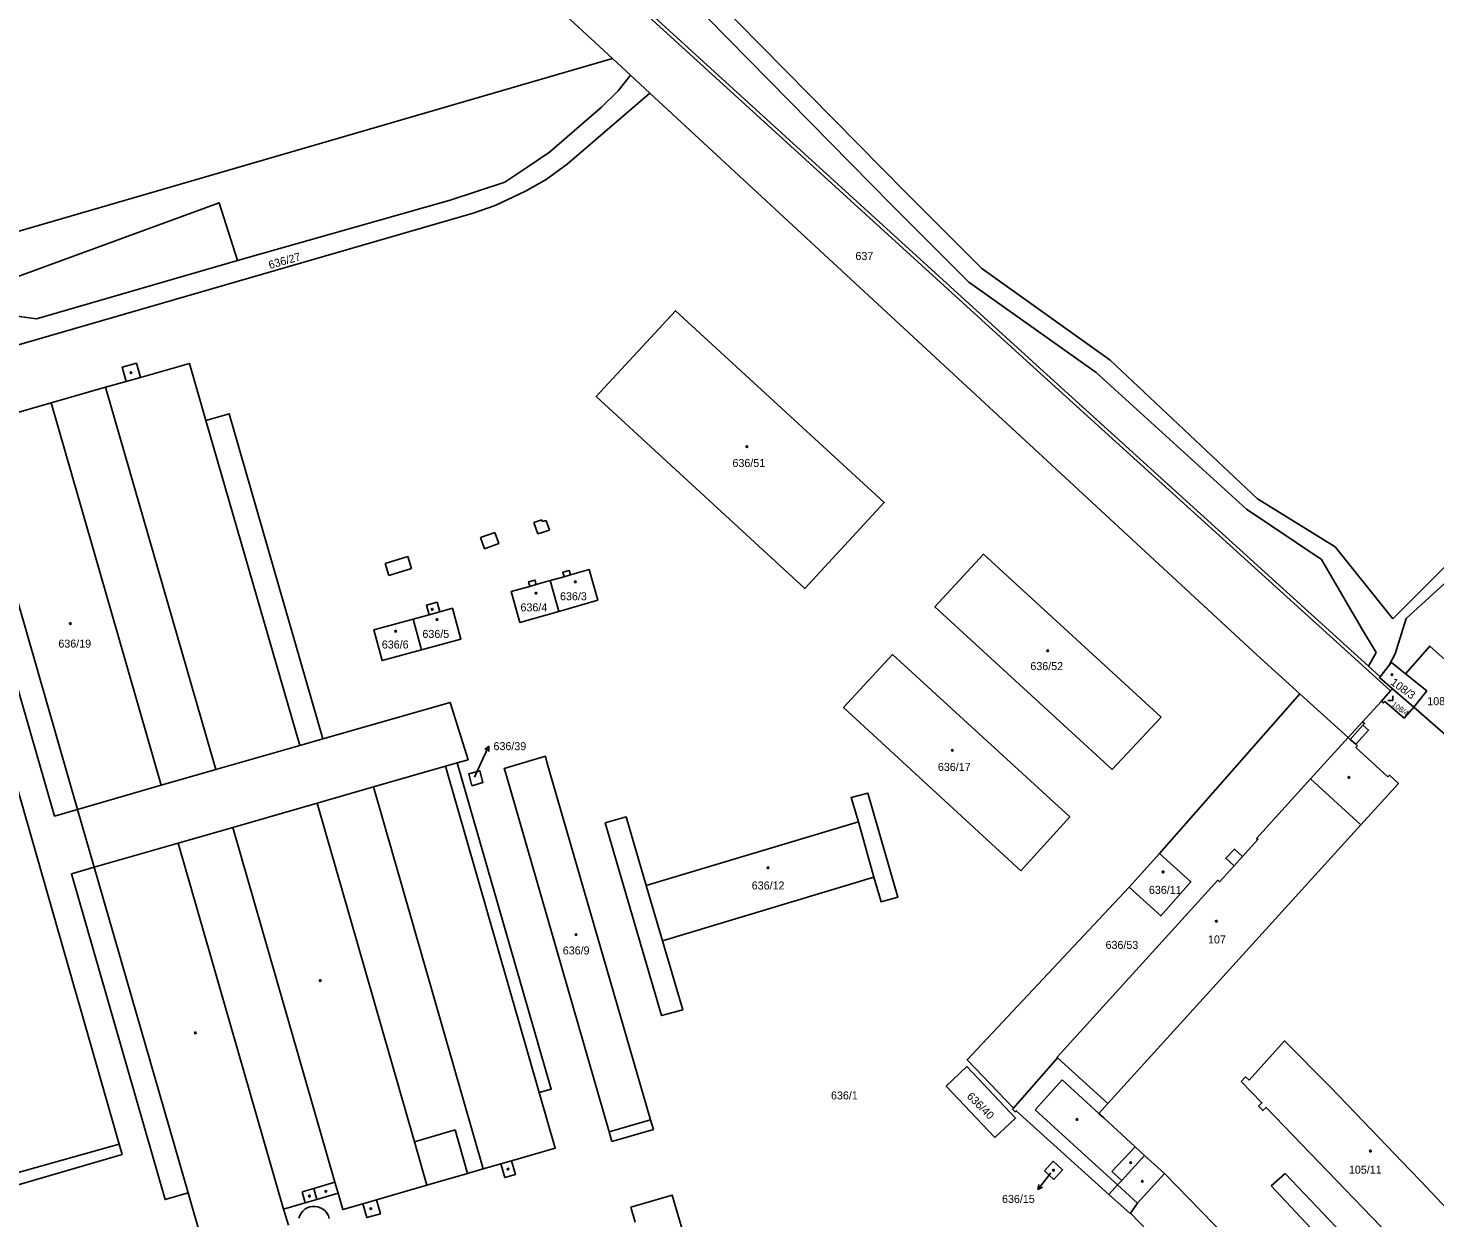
# Model space of a CAD drawing. Extents: x -724107 to -720612, y -1045267 to -1038441.
# Drawn here: x -723704.7 to -723405.8, y -1042386.8 to -1042134.1 of the extents above; entities that cross this region are included whole.
import ezdxf

# ---------------------------------------------------------------- set-up
doc = ezdxf.new("R2010")
doc.units = 0
for name, color, linetype in [('Hranice parcel', 7, 'Continuous'), ('Parcelní čísla', 7, 'Continuous'), ('Pop  PČ popisy', 7, 'Continuous'), ('Vnitřní kresba', 7, 'Continuous'), ('Značky budov', 7, 'Continuous'), ('Značky kultur', 7, 'Continuous')]:
    doc.layers.add(name, color=color, linetype=linetype)

msp = doc.modelspace()

# ---------------------------------------------------------------- linework, layer by layer
at = {"layer": 'Hranice parcel'}
for p, q in [((-723580.53, -1042140.52), (-723576.72, -1042144.04)), ((-723572.57, -1042147.88), (-723576.72, -1042144.04)), ((-723593.78, -1042251.46), (-723591.91, -1042257.99)), ((-723622.86, -1042259.66), (-723621.08, -1042266.16)), ((-723464.29, -1042309.43), (-723434.48, -1042275.51)), ((-723434.48, -1042275.51), (-723424.2, -1042284.81)), ((-723417.14, -1042277.06), (-723415.2, -1042274.86)), ((-723415.2, -1042274.86), (-723414.81, -1042274.43)), ((-723414.81, -1042274.43), (-723410.25, -1042278.31)), ((-723417.14, -1042277.06), (-723421.15, -1042281.44)), ((-723403.49, -1042284.29), (-723410.25, -1042278.31)), ((-723421.15, -1042281.44), (-723424.2, -1042284.81)), ((-723470.72, -1042316.61), (-723464.29, -1042309.43)), ((-723470.44, -1042385.85), (-723434.75, -1042422.79))]:
    msp.add_line(p, q, dxfattribs=at)
for points in [[(-723580.53, -1042140.52), (-723593.18, -1042128.83), (-723592.44, -1042128.03), (-723638.44, -1042085.96)], [(-723616.6, -1042091.67), (-723491.76, -1042205.44), (-723415.2, -1042274.86)], [(-723752.26, -1042388.65), (-723794.21, -1042239.21), (-723774.95, -1042210.3), (-723755.82, -1042191.53), (-723580.53, -1042140.52)], [(-723576.72, -1042144.04), (-723579.32, -1042147.4), (-723582.86, -1042150.85), (-723593.88, -1042160.43), (-723598.68, -1042163.71), (-723603.35, -1042166.78), (-723615.02, -1042170.65), (-723660.16, -1042183.43)], [(-723572.57, -1042147.88), (-723590.15, -1042162.97), (-723594.6, -1042166.26), (-723598.96, -1042168.74), (-723605.41, -1042171.73), (-723610.13, -1042173.4), (-723721.23, -1042205.57), (-723722.93, -1042200.18)], [(-723434.48, -1042275.51), (-723443.58, -1042267.28), (-723572.57, -1042147.88)], [(-723660.16, -1042183.43), (-723664.06, -1042171.21), (-723773.61, -1042211.26), (-723762.13, -1042260.47), (-723729.35, -1042383.79)], [(-723719.02, -1042195.22), (-723714.92, -1042194.19), (-723702.88, -1042195.87), (-723660.16, -1042183.43)], [(-723583.96, -1042212.37), (-723567.1, -1042194.11), (-723522.78, -1042234.83), (-723539.66, -1042253.16), (-723583.96, -1042212.37)], [(-723683.82, -1042209.15), (-723684.68, -1042206.14), (-723681.67, -1042205.28), (-723680.81, -1042208.29), (-723670.4, -1042205.31), (-723666.9, -1042217.41), (-723661.96, -1042215.99), (-723642.02, -1042285.04), (-723614.99, -1042277.32), (-723611.21, -1042289.51), (-723613.48, -1042290.17), (-723593.52, -1042359.52), (-723596.06, -1042360.24), (-723592.66, -1042372.05), (-723601.95, -1042374.73), (-723601.12, -1042377.61), (-723603.42, -1042378.27), (-723604.25, -1042375.39), (-723607.96, -1042376.46), (-723611.3, -1042377.41), (-723619.93, -1042379.93), (-723630.68, -1042383.03), (-723629.83, -1042385.98), (-723632.73, -1042386.78), (-723633.57, -1042383.87), (-723637.8, -1042385.09), (-723638.8, -1042381.63), (-723643.31, -1042382.93), (-723645.77, -1042383.64), (-723650.38, -1042384.97), (-723649.38, -1042388.43)], [(-723717.55, -1042218.8), (-723699.78, -1042213.7), (-723688.21, -1042210.39), (-723683.82, -1042209.15)], [(-723667.21, -1042393.61), (-723670.68, -1042381.55), (-723675.57, -1042382.96), (-723695.45, -1042313.75), (-723690.61, -1042312.35), (-723694.16, -1042300.06), (-723699.05, -1042301.47), (-723719, -1042232.23)], [(-723725.77, -1042382.51), (-723760.84, -1042260.11), (-723761.97, -1042256.16), (-723721.65, -1042244.41), (-723720.39, -1042248.8), (-723685.32, -1042371.19), (-723684.7, -1042373.37), (-723725.02, -1042385.12), (-723725.77, -1042382.51)], [(-723463.98, -1042280.49), (-723474.35, -1042291.57), (-723512.01, -1042257.05), (-723501.68, -1042245.85), (-723463.98, -1042280.49)], [(-723591.91, -1042257.99), (-723600.23, -1042260.35), (-723602.02, -1042253.78), (-723598.06, -1042252.67), (-723598.34, -1042251.71), (-723596.98, -1042251.33), (-723596.72, -1042252.29), (-723593.78, -1042251.46)], [(-723593.78, -1042251.46), (-723590.8, -1042250.62), (-723591.08, -1042249.66), (-723589.73, -1042249.28), (-723589.46, -1042250.25), (-723585.45, -1042249.12), (-723583.6, -1042255.62), (-723591.91, -1042257.99)], [(-723622.86, -1042259.66), (-723619.48, -1042258.71), (-723620.05, -1042256.67), (-723617.78, -1042256.04), (-723617.21, -1042258.08), (-723614.52, -1042257.32), (-723612.73, -1042263.9), (-723621.08, -1042266.16)], [(-723621.08, -1042266.16), (-723629.45, -1042268.44), (-723631.23, -1042261.91), (-723622.86, -1042259.66)], [(-723395.57, -1042275.54), (-723406.89, -1042265.36), (-723412.03, -1042271.25)], [(-723493.76, -1042313.1), (-723531.43, -1042278.38), (-723521.01, -1042267.16), (-723483.37, -1042301.67), (-723493.76, -1042313.1)], [(-723414.81, -1042274.43), (-723417.58, -1042272.07), (-723417.44, -1042271.89), (-723415.48, -1042269.43), (-723415, -1042268.83), (-723412.03, -1042271.25)], [(-723412.03, -1042271.25), (-723407.54, -1042274.89), (-723410.25, -1042278.31)], [(-723410.25, -1042278.31), (-723412.34, -1042280.67), (-723416.42, -1042277.11), (-723416.73, -1042277.44), (-723417.14, -1042277.06)], [(-723421.15, -1042281.44), (-723420.74, -1042281.81), (-723421.07, -1042282.19), (-723419.89, -1042283.22), (-723422.62, -1042286.2), (-723422.25, -1042286.54), (-723422.58, -1042286.89), (-723415.76, -1042293.14), (-723415.45, -1042292.81), (-723413.54, -1042294.56), (-723421.5, -1042303.32), (-723475.26, -1042362.53), (-723477.17, -1042364.64), (-723476.15, -1042365.58), (-723469.5, -1042371.73), (-723467.47, -1042373.59), (-723463.24, -1042377.45), (-723468.96, -1042383.7), (-723470.44, -1042385.85)], [(-723424.2, -1042284.81), (-723432.19, -1042293.58), (-723443.69, -1042306.21), (-723443.38, -1042306.49), (-723446.65, -1042310.08), (-723448.37, -1042308.51), (-723450.21, -1042310.45), (-723448.45, -1042312.06), (-723451.54, -1042315.45), (-723451.91, -1042315.11), (-723486.06, -1042352.72), (-723485.95, -1042352.82), (-723495.35, -1042363.54)], [(-723580.62, -1042370.6), (-723581.19, -1042368.54), (-723603.16, -1042292.47), (-723603.5, -1042291.37), (-723594.77, -1042288.78), (-723594.49, -1042290.03), (-723572.41, -1042366), (-723571.82, -1042368.06), (-723580.62, -1042370.6)], [(-723610.38, -1042295.02), (-723611.06, -1042292.52), (-723608.71, -1042291.84), (-723608.04, -1042294.35), (-723610.38, -1042295.02)], [(-723528.26, -1042302.67), (-723529.84, -1042297.52), (-723526.25, -1042296.62), (-723519.88, -1042318.73), (-723523.46, -1042319.72), (-723524.99, -1042314.48), (-723569.89, -1042328), (-723565.6, -1042342.68), (-723570.08, -1042343.88), (-723582.06, -1042302.95), (-723577.59, -1042301.65), (-723573.33, -1042316.24), (-723528.26, -1042302.67)], [(-723470.72, -1042316.61), (-723464.05, -1042322.7), (-723457.61, -1042315.43), (-723464.29, -1042309.43)], [(-723495.35, -1042363.54), (-723505.18, -1042353.25), (-723470.72, -1042316.61)], [(-723407.9, -1042398.37), (-723441.65, -1042363.37), (-723442.37, -1042364.06), (-723443.24, -1042363.09), (-723442.55, -1042362.43), (-723446.93, -1042357.89), (-723446.02, -1042356.89), (-723445.28, -1042357.56), (-723437.77, -1042349.26), (-723427.94, -1042359.05), (-723422.7, -1042364.52), (-723411.02, -1042376.73), (-723408.74, -1042379.11), (-723398.9, -1042389.57)], [(-723499.25, -1042369.8), (-723509.59, -1042358.88), (-723505.2, -1042354.68), (-723494.86, -1042365.66), (-723499.25, -1042369.8)], [(-723495.35, -1042363.54), (-723495.56, -1042363.78), (-723494.97, -1042364.32), (-723494.75, -1042364.08), (-723475.08, -1042381.86), (-723470.56, -1042385.95), (-723470.44, -1042385.85)], [(-723488.75, -1042376.85), (-723486.9, -1042374.81), (-723484.89, -1042376.63), (-723486.73, -1042378.67), (-723488.75, -1042376.85)], [(-723575.68, -1042387.77), (-723576.59, -1042384.58), (-723567.82, -1042382.02), (-723565.46, -1042390.21)], [(-723647.16, -1042386.91), (-723646.97, -1042386.36), (-723646.68, -1042385.86), (-723646.31, -1042385.41), (-723645.88, -1042385.03), (-723645.38, -1042384.74), (-723644.84, -1042384.53), (-723644.27, -1042384.43), (-723643.69, -1042384.42), (-723643.12, -1042384.51), (-723642.97, -1042384.55), (-723642.43, -1042384.76), (-723641.94, -1042385.06), (-723641.51, -1042385.45), (-723641.15, -1042385.9), (-723640.87, -1042386.41), (-723640.68, -1042386.95)]]:
    msp.add_lwpolyline(points, dxfattribs=at)
at = {"layer": 'Pop  PČ popisy'}
for p, q in [((-723608.05, -1042289.35), (-723606.78, -1042286.63)), ((-723606.78, -1042286.63), (-723607.66, -1042287.33)), ((-723606.78, -1042286.63), (-723606.75, -1042287.75)), ((-723609.81, -1042293.19), (-723608.05, -1042289.35)), ((-723487.42, -1042377.3), (-723488.32, -1042378.46)), ((-723488.32, -1042378.46), (-723490.17, -1042380.83)), ((-723490.17, -1042380.83), (-723489.95, -1042379.73)), ((-723490.17, -1042380.83), (-723489.16, -1042380.34))]:
    msp.add_line(p, q, dxfattribs=at)
at = {"layer": 'Vnitřní kresba'}
for p, q in [((-723615.9, -1042091.33), (-723491.28, -1042204.91)), ((-723564.33, -1042122.2), (-723518.13, -1042169.06)), ((-723521.14, -1042171.72), (-723566.34, -1042125.75)), ((-723518.13, -1042169.06), (-723502.06, -1042185.13)), ((-723504.78, -1042188.04), (-723521.14, -1042171.72)), ((-723502.06, -1042185.13), (-723474.8, -1042204.59)), ((-723504.78, -1042188.04), (-723477.77, -1042207.24)), ((-723491.28, -1042204.91), (-723419.91, -1042269.64)), ((-723474.8, -1042204.59), (-723443.47, -1042234.07)), ((-723683.82, -1042209.15), (-723680.81, -1042208.29)), ((-723477.77, -1042207.24), (-723445.81, -1042236.25)), ((-723664.79, -1042291.61), (-723688.21, -1042210.39)), ((-723676.37, -1042294.94), (-723699.78, -1042213.7)), ((-723666.9, -1042217.41), (-723646.96, -1042286.48)), ((-723381.46, -1042226.19), (-723414.7, -1042259.61)), ((-723714.1, -1042230.82), (-723694.16, -1042300.06)), ((-723378.76, -1042229.13), (-723411.88, -1042259.5)), ((-723429.85, -1042246.98), (-723445.81, -1042236.25)), ((-723427, -1042244.26), (-723443.47, -1042234.07)), ((-723595.49, -1042238.54), (-723597.24, -1042239.11)), ((-723597.24, -1042239.11), (-723596.4, -1042241.54)), ((-723595.37, -1042238.92), (-723595.49, -1042238.54)), ((-723594.61, -1042238.67), (-723595.37, -1042238.92)), ((-723593.93, -1042240.73), (-723594.61, -1042238.67)), ((-723608.58, -1042242.32), (-723605.52, -1042241.21)), ((-723607.7, -1042244.72), (-723608.58, -1042242.32)), ((-723605.52, -1042241.21), (-723604.65, -1042243.59)), ((-723596.4, -1042241.54), (-723593.93, -1042240.73)), ((-723604.65, -1042243.59), (-723607.7, -1042244.72)), ((-723414.7, -1042259.61), (-723427, -1042244.26)), ((-723624.02, -1042246.36), (-723628.8, -1042247.83)), ((-723628.8, -1042247.83), (-723628.03, -1042250.39)), ((-723628.03, -1042250.39), (-723623.23, -1042248.91)), ((-723623.23, -1042248.91), (-723624.02, -1042246.36)), ((-723421.42, -1042261.59), (-723429.85, -1042246.98)), ((-723590.8, -1042250.62), (-723589.46, -1042250.25)), ((-723598.06, -1042252.67), (-723596.72, -1042252.29)), ((-723619.48, -1042258.71), (-723617.21, -1042258.08)), ((-723411.88, -1042259.5), (-723414.26, -1042267.01)), ((-723418.3, -1042266.74), (-723421.42, -1042261.59)), ((-723418.3, -1042266.74), (-723419.91, -1042269.64)), ((-723417.44, -1042271.89), (-723419.91, -1042269.64)), ((-723414.26, -1042267.01), (-723415.48, -1042269.43)), ((-723421.07, -1042282.19), (-723423.78, -1042285.19)), ((-723664.79, -1042291.61), (-723646.96, -1042286.48)), ((-723646.96, -1042286.48), (-723642.02, -1042285.04)), ((-723424.2, -1042284.81), (-723423.78, -1042285.19)), ((-723422.62, -1042286.2), (-723423.78, -1042285.19)), ((-723616.02, -1042290.9), (-723613.48, -1042290.17)), ((-723676.37, -1042294.94), (-723664.79, -1042291.61)), ((-723631.26, -1042295.28), (-723616.02, -1042290.9)), ((-723616.02, -1042290.9), (-723596.06, -1042360.24)), ((-723432.19, -1042293.58), (-723421.5, -1042303.32)), ((-723694.16, -1042300.06), (-723676.37, -1042294.94)), ((-723643.23, -1042298.72), (-723631.26, -1042295.28)), ((-723607.96, -1042376.46), (-723631.26, -1042295.28)), ((-723661.2, -1042303.89), (-723643.23, -1042298.72)), ((-723622.6, -1042370.67), (-723643.23, -1042298.72)), ((-723528.26, -1042302.67), (-723524.99, -1042314.48)), ((-723672.77, -1042307.23), (-723661.2, -1042303.89)), ((-723639.48, -1042379.29), (-723661.2, -1042303.89)), ((-723690.61, -1042312.35), (-723672.77, -1042307.23)), ((-723672.77, -1042307.23), (-723650.38, -1042384.97)), ((-723448.45, -1042312.06), (-723446.65, -1042310.08)), ((-723690.61, -1042312.35), (-723670.68, -1042381.55)), ((-723573.33, -1042316.24), (-723569.89, -1042328)), ((-723475.26, -1042362.53), (-723485.95, -1042352.82)), ((-723484.95, -1042357.54), (-723488.67, -1042361.62)), ((-723477.17, -1042364.64), (-723484.95, -1042357.54)), ((-723488.67, -1042361.62), (-723490.72, -1042363.87)), ((-723490.72, -1042363.87), (-723480.14, -1042373.51)), ((-723622.6, -1042370.67), (-723613.97, -1042368.17)), ((-723613.97, -1042368.17), (-723611.3, -1042377.41)), ((-723581.19, -1042368.54), (-723572.41, -1042366)), ((-723685.32, -1042371.19), (-723725.53, -1042382.43)), ((-723619.93, -1042379.93), (-723622.6, -1042370.67)), ((-723480.14, -1042373.51), (-723473.21, -1042379.82)), ((-723469.5, -1042371.73), (-723474.41, -1042377)), ((-723467.47, -1042373.59), (-723472.33, -1042378.93)), ((-723604.25, -1042375.39), (-723601.95, -1042374.73)), ((-723474.41, -1042377), (-723472.33, -1042378.93)), ((-723440.58, -1042380.06), (-723437.63, -1042377.42)), ((-723437.63, -1042377.42), (-723424.1, -1042391.65)), ((-723643.99, -1042380.59), (-723639.48, -1042379.29)), ((-723639.48, -1042379.29), (-723638.8, -1042381.63)), ((-723475.08, -1042381.86), (-723473.21, -1042379.82)), ((-723473.21, -1042379.82), (-723472.33, -1042378.93)), ((-723473.21, -1042379.82), (-723468.96, -1042383.7)), ((-723425.98, -1042415.53), (-723463.24, -1042377.45)), ((-723440.58, -1042380.06), (-723427.06, -1042394.41)), ((-723646.44, -1042381.29), (-723643.99, -1042380.59)), ((-723645.77, -1042383.64), (-723646.44, -1042381.29)), ((-723643.99, -1042380.59), (-723643.31, -1042382.93)), ((-723633.57, -1042383.87), (-723630.68, -1042383.03))]:
    msp.add_line(p, q, dxfattribs=at)
at = {"layer": 'Značky budov'}
for centre in [(-723682.79, -1042207.26), (-723551.96, -1042222.98), (-723588.42, -1042251.7), (-723596.78, -1042254.12), (-723618.81, -1042257.55), (-723695.7, -1042260.58), (-723617.78, -1042259.73), (-723626.56, -1042262.2), (-723488.07, -1042266.36), (-723414.9, -1042271.45), (-723508.33, -1042287.51), (-723424.07, -1042293.27), (-723547.49, -1042312.47), (-723463.54, -1042313.34), (-723588.27, -1042326.68), (-723452.23, -1042323.82), (-723642.6, -1042336.42), (-723669.13, -1042347.54), (-723481.82, -1042365.93), (-723419.49, -1042372.67), (-723602.73, -1042376.49), (-723486.83, -1042376.72), (-723470.42, -1042375.1), (-723467.94, -1042379.07), (-723644.89, -1042382.23), (-723641.41, -1042381.22), (-723631.86, -1042384.9)]:
    msp.add_circle(centre, 0.175, dxfattribs=at)
at = {"layer": 'Značky kultur'}
for p, q in [((-723415.76, -1042276.96), (-723414.76, -1042276.96)), ((-723414.76, -1042276.96), (-723414.76, -1042275.96))]:
    msp.add_line(p, q, dxfattribs=at)

# ---------------------------------------------------------------- texts
at = {"layer": 'Parcelní čísla'}
for s, height, rotation, p in [('636/27', 1.7, 16, (-723653.29, -1042185.26)), ('108/3', 1.7, 324, (-723415.36, -1042273.41)), ('108/4', 1.139, 324, (-723415.06, -1042277.98)), ('636/40', 1.7, 315, (-723505.37, -1042361.16))]:
    msp.add_text(s, height=height, rotation=rotation, dxfattribs=at).set_placement(p)
for s, p in [('637', (-723528.9, -1042183.33)), ('636/51', (-723555.02, -1042227.31)), ('636/3', (-723591.66, -1042255.63)), ('636/4', (-723600.06, -1042257.98)), ('636/5', (-723620.89, -1042263.63)), ('636/19', (-723698.23, -1042265.69)), ('636/6', (-723629.52, -1042265.88)), ('636/52', (-723491.73, -1042270.47)), ('108/2', (-723407.42, -1042277.92)), ('636/39', (-723605.79, -1042287.48)), ('636/17', (-723511.38, -1042291.89)), ('636/12', (-723550.93, -1042317.08)), ('636/11', (-723466.55, -1042318.01)), ('636/9', (-723591.08, -1042330.88)), ('636/53', (-723475.76, -1042329.7)), ('107', (-723453.99, -1042328.54)), ('636/1', (-723534.09, -1042361.68)), ('105/11', (-723424.06, -1042377.45)), ('636/15', (-723497.76, -1042383.67))]:
    msp.add_text(s, height=1.7, dxfattribs=at).set_placement(p)

doc.saveas('drawing.dxf')
